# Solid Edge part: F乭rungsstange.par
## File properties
Username: bmolnar
Dokumentum tartalom típus: 0
Author: bmolnar
Last saved by: bmolnar
Revision: 80
Sűrűség: 0,000 kg/m^3
Pontosság: 0,990
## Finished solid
Body 1: solid body, 8 faces, 7 edges, 4 vertices.
  Faces by surface: cone 4, cylinder 2, plane 2
  Edges by curve: circle 7
Bounding box of the edges (mm): 5.000 x 5.000 x 68.000, from (-2.5, -2.5, -44) to (2.5, 2.5, 24).
Cylindrical faces by radius (mm): R1.2295 x1, R2.5 x1
Conical faces (half-angle, radius in mm at the cone's reference point): 45 deg R1.3295 x1, 45 deg R2.25 x1, 45 deg R2.5 x1, 59 deg R0.6148 x1
Planar faces by outward normal: +z 1, -z 1
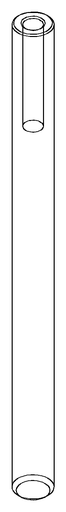
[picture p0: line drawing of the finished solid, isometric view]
